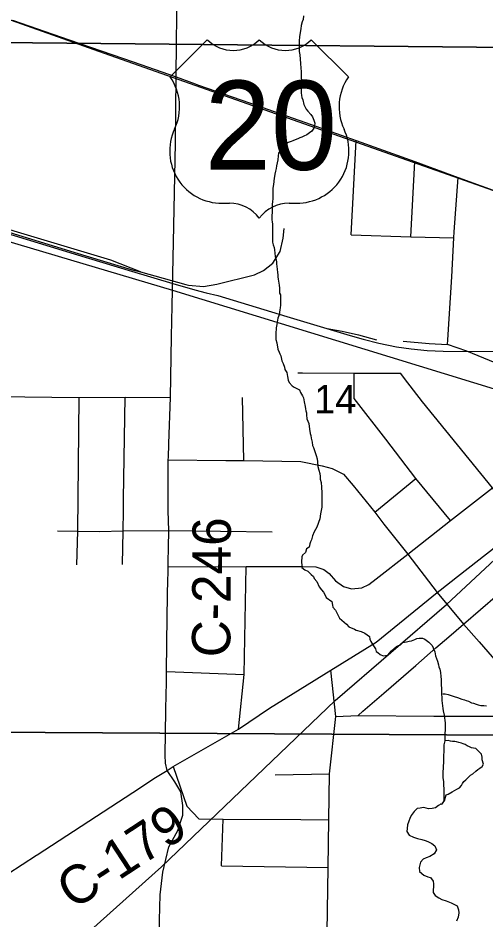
# Model space of a CAD drawing. Extents: x 0 to 34, y 0 to 22.
# Drawn here: x 6.537 to 7.229, y 17.171 to 18.505 of the extents above; entities that cross this region are included whole.
import ezdxf

# ---------------------------------------------------------------- set-up
doc = ezdxf.new("R2010")
doc.units = 0
for name, color, linetype in [('GM_X_City_Street', 7, 'Continuous'), ('GM_X_County_Road', 7, 'Continuous'), ('GM_X_County_Road_Text', 7, 'Continuous'), ('GM_X_Minor_River', 7, 'Continuous'), ('GM_X_Rail_Line', 7, 'Continuous'), ('GM_X_Section', 7, 'Continuous'), ('GM_X_Section_Text', 7, 'Continuous'), ('GM_X_Township_Road', 7, 'Continuous'), ('GM_X_US_Location', 7, 'Continuous'), ('GM_X_US_Route', 7, 'Continuous'), ('GM_X_US_Shield', 7, 'Continuous')]:
    doc.layers.add(name, color=color, linetype=linetype)

msp = doc.modelspace()

# ---------------------------------------------------------------- linework, layer by layer
at = {"layer": 'GM_X_City_Street'}
for p, q in [((7.0299, 18.1841), (7.0374, 18.3239)), ((7.1181, 18.1814), (7.1241, 18.2926)), ((6.8714, 17.8506), (6.8692, 17.9435)), ((7.0648, 17.774), (7.1257, 17.8238)), ((6.7603, 17.7469), (6.9132, 17.7448)), ((6.7567, 17.5386), (6.8716, 17.534)), ((6.9176, 17.3858), (6.9978, 17.387)), ((6.838, 17.2511), (6.8405, 17.3201)), ((6.838, 17.2511), (6.9958, 17.2486))]:
    msp.add_line(p, q, dxfattribs=at)
for points in [[(7.0299, 18.1841), (7.1181, 18.1814), (7.1818, 18.1799)], [(7.1068, 18.0268), (7.1456, 18.0236), (7.1726, 18.0219)], [(7.2836, 17.7541), (7.2391, 17.8103), (7.1354, 17.9374), (7.109, 17.9718), (7.1035, 17.9791), (7.0343, 17.9794), (6.9579, 17.9797), (6.9509, 17.9797)], [(7.1768, 17.7617), (7.1257, 17.8238), (7.0811, 17.8823), (7.0342, 17.9423), (7.0343, 17.9794)], [(6.7594, 17.8514), (6.8445, 17.8503), (6.8714, 17.8506), (6.9553, 17.8489), (6.9869, 17.8427), (7.0017, 17.8385), (7.0187, 17.8302), (7.0332, 17.8134), (7.0648, 17.774), (7.0782, 17.7562), (7.1139, 17.7119), (7.1572, 17.6552), (7.1963, 17.6084), (7.2194, 17.5823), (7.2451, 17.5529), (7.2515, 17.5456), (7.2556, 17.5403), (7.2576, 17.5341), (7.2582, 17.523), (7.2569, 17.4725), (7.2511, 17.4066)], [(7.0405, 17.4732), (7.0472, 17.4797), (7.0785, 17.5066), (7.1258, 17.5472), (7.1555, 17.5732), (7.1743, 17.5898), (7.1963, 17.6084), (7.2467, 17.6518), (7.3835, 17.7695), (7.3914, 17.7751), (7.4006, 17.7802), (7.4207, 17.7892), (7.4647, 17.8093), (7.5075, 17.8298), (7.513, 17.8322)], [(6.7593, 17.6931), (6.8745, 17.6936), (6.9179, 17.6936), (6.9583, 17.6938), (6.9776, 17.6931), (6.9897, 17.6892), (6.9975, 17.6834), (7.0069, 17.6724), (7.0186, 17.664), (7.0303, 17.6607), (7.0459, 17.6621), (7.0561, 17.6672), (7.0669, 17.6754), (7.1139, 17.7119), (7.1768, 17.7617), (7.2391, 17.8103)], [(6.8632, 17.4533), (6.8716, 17.534), (6.8745, 17.6936)], [(7.0072, 17.472), (7.0405, 17.4732), (7.1522, 17.4725), (7.2569, 17.4725), (7.3227, 17.4727)], [(6.7665, 17.3977), (6.7867, 17.3393), (6.8048, 17.3204), (6.8405, 17.3201), (6.9556, 17.3194), (6.9968, 17.319)]]:
    msp.add_lwpolyline(points, dxfattribs=at)
at = {"layer": 'GM_X_County_Road'}
for p, q in [((7.1825, 18.1889), (7.1881, 18.2693)), ((6.7624, 17.9435), (6.7641, 18.0341)), ((6.4655, 17.9453), (6.6276, 17.9439)), ((6.7595, 17.8553), (6.7602, 17.8746)), ((6.7405, 17.3814), (6.7575, 17.3922)), ((6.7067, 17.3597), (6.7405, 17.3814)), ((6.5219, 17.2393), (6.5642, 17.2669))]:
    msp.add_line(p, q, dxfattribs=at)
for points in [[(6.7641, 18.0341), (6.7649, 18.0794), (6.7671, 18.1737), (6.7702, 18.3199), (6.7709, 18.4179)], [(7.173, 18.0289), (7.179, 18.1222), (7.1818, 18.1799), (7.1825, 18.1889)], [(7.3075, 17.9794), (7.2872, 17.9796), (7.2731, 17.9796), (7.2661, 17.9826), (7.2431, 17.995), (7.2012, 18.012), (7.1726, 18.0219), (7.173, 18.0289)], [(6.6276, 17.9439), (6.6953, 17.9441), (6.7624, 17.9435)], [(6.7602, 17.8746), (6.7602, 17.8756), (6.7624, 17.9435)], [(7.1618, 17.6588), (7.1875, 17.6787), (7.246, 17.7246), (7.2836, 17.7541), (7.3286, 17.7895), (7.3789, 17.8287), (7.3933, 17.8405), (7.4314, 17.8737), (7.452, 17.8902), (7.4686, 17.899), (7.4829, 17.9074), (7.5178, 17.9352)], [(6.7593, 17.8347), (6.7593, 17.8367), (6.7594, 17.8514), (6.7595, 17.8553)], [(6.7594, 17.776), (6.7593, 17.778), (6.759, 17.7887), (6.7593, 17.8347)], [(6.7593, 17.697), (6.7594, 17.7), (6.7596, 17.7216), (6.7603, 17.7469), (6.7594, 17.776)], [(6.7589, 17.6775), (6.759, 17.6804), (6.7593, 17.6931), (6.7593, 17.697)], [(6.7565, 17.5201), (6.7566, 17.525), (6.7567, 17.5386), (6.7576, 17.62), (6.7589, 17.6775)], [(6.7575, 17.3922), (6.7665, 17.3977), (6.8632, 17.4533), (6.9092, 17.4844), (7, 17.5404), (7.0669, 17.5816), (7.1572, 17.6552), (7.1618, 17.6588)], [(6.9943, 16.6777), (6.9929, 17.0382), (6.994, 17.1215), (6.9958, 17.2486), (6.9968, 17.319), (6.9978, 17.387), (7.0072, 17.472), (7, 17.5404)], [(6.7559, 17.4808), (6.7564, 17.5055), (6.7565, 17.5201)], [(6.7575, 17.3922), (6.7551, 17.4027), (6.7546, 17.4145), (6.7559, 17.4808)], [(6.7374, 17.0638), (6.7393, 17.0697), (6.7425, 17.084), (6.7456, 17.1033), (6.7462, 17.1319), (6.7464, 17.1706), (6.7473, 17.2079), (6.7515, 17.2415), (6.7604, 17.279), (6.7736, 17.3034), (6.7807, 17.3258), (6.7807, 17.3402), (6.7779, 17.3604), (6.7688, 17.3754), (6.7575, 17.3922)], [(6.5642, 17.2669), (6.5651, 17.2675), (6.7067, 17.3597)]]:
    msp.add_lwpolyline(points, dxfattribs=at)
at = {"layer": 'GM_X_Minor_River'}
for points in [[(6.9593, 18.5082), (6.9589, 18.5028), (6.9574, 18.4994), (6.9559, 18.4941), (6.9556, 18.4892), (6.9544, 18.4838), (6.9533, 18.477), (6.953, 18.4713), (6.9531, 18.4553), (6.9542, 18.4504), (6.9551, 18.4379), (6.9555, 18.4307), (6.9559, 18.4261), (6.9559, 18.4193), (6.9563, 18.4102), (6.9564, 18.4041), (6.956, 18.3984), (6.956, 18.3942), (6.9564, 18.3904), (6.9568, 18.3874), (6.9584, 18.384), (6.9599, 18.3771), (6.9634, 18.3703), (6.966, 18.3673), (6.9702, 18.3624), (6.9729, 18.3586), (6.9748, 18.3537), (6.976, 18.3495), (6.9756, 18.3453), (6.9749, 18.3419), (6.9719, 18.3377), (6.9685, 18.335), (6.9643, 18.3323), (6.9601, 18.3304), (6.9571, 18.3289), (6.9541, 18.3277), (6.9511, 18.3262), (6.9473, 18.3247), (6.9439, 18.3231), (6.9412, 18.3224), (6.937, 18.3208), (6.9344, 18.3193), (6.9317, 18.3162), (6.9291, 18.3136), (6.9265, 18.3113), (6.9242, 18.3082), (6.9227, 18.3052), (6.9219, 18.301), (6.9216, 18.2953), (6.9194, 18.2862), (6.919, 18.2824), (6.9179, 18.2786), (6.9168, 18.274), (6.9164, 18.2706), (6.916, 18.2679), (6.9153, 18.2588), (6.9142, 18.2535), (6.9142, 18.2455), (6.9139, 18.2406), (6.9139, 18.2379), (6.9136, 18.233), (6.9132, 18.2295), (6.9132, 18.2257), (6.9129, 18.2212), (6.9129, 18.2166), (6.9125, 18.2132), (6.9125, 18.2064), (6.9129, 18.2033), (6.9137, 18.1999), (6.9138, 18.1882), (6.9138, 18.1844), (6.9138, 18.1737), (6.9146, 18.1695), (6.9158, 18.1654), (6.9166, 18.1623), (6.917, 18.157), (6.9177, 18.1525), (6.9189, 18.1472), (6.9193, 18.1441), (6.9197, 18.1415), (6.9201, 18.1377), (6.9205, 18.1335), (6.9209, 18.1286), (6.9217, 18.1251), (6.9217, 18.1221), (6.9221, 18.1187), (6.9229, 18.113), (6.9233, 18.11), (6.9237, 18.1054), (6.9237, 18.1008), (6.9241, 18.0982), (6.9252, 18.0955), (6.9253, 18.0803), (6.925, 18.0762), (6.9246, 18.0735), (6.9235, 18.0659), (6.9216, 18.0609), (6.9205, 18.0552), (6.9201, 18.0518), (6.919, 18.0469), (6.9187, 18.0381)], [(6.9187, 18.0381), (6.9183, 18.0324), (6.9187, 18.0294), (6.9199, 18.0245), (6.9215, 18.0154), (6.9234, 18.0108), (6.9242, 18.0082), (6.9257, 18.0055), (6.9272, 17.9979), (6.9292, 17.9938), (6.9315, 17.9888), (6.9319, 17.985), (6.9349, 17.9805), (6.9357, 17.9748), (6.9369, 17.9695), (6.938, 17.9657), (6.9426, 17.9608), (6.9457, 17.9589), (6.9506, 17.9563), (6.9533, 17.9551), (6.9552, 17.9513), (6.9582, 17.946), (6.9594, 17.943), (6.9606, 17.9373), (6.9617, 17.9305), (6.9625, 17.9267), (6.9629, 17.924), (6.9637, 17.921), (6.9641, 17.9183), (6.9645, 17.9123), (6.9672, 17.9051), (6.9684, 17.8971), (6.9691, 17.8903), (6.9703, 17.8876), (6.9707, 17.8838), (6.9723, 17.8774), (6.973, 17.8728), (6.9742, 17.8698), (6.9761, 17.8637), (6.978, 17.858), (6.9796, 17.8531), (6.9804, 17.8485), (6.9808, 17.8417), (6.9819, 17.8364), (6.9835, 17.8311), (6.9839, 17.8269), (6.9843, 17.8231), (6.9855, 17.8178), (6.9859, 17.8113), (6.9863, 17.8087), (6.9867, 17.8053), (6.9868, 17.7859), (6.9864, 17.7813), (6.9845, 17.7714), (6.9838, 17.7642), (6.9793, 17.752), (6.9752, 17.7448), (6.9729, 17.7391), (6.9714, 17.7334), (6.9699, 17.7304), (6.9688, 17.7273), (6.9677, 17.7224), (6.9639, 17.7197), (6.9624, 17.7144), (6.9579, 17.7105), (6.9568, 17.7079), (6.9564, 17.7007), (6.9572, 17.695), (6.9572, 17.6923), (6.9614, 17.6889), (6.966, 17.687), (6.9706, 17.6817), (6.9744, 17.6791), (6.9751, 17.6761), (6.9793, 17.6715), (6.9824, 17.6639), (6.9862, 17.659), (6.9889, 17.656), (6.9912, 17.6522), (6.9931, 17.648), (7.0015, 17.642), (7.0023, 17.6367), (7.0027, 17.6337), (7.0069, 17.6291), (7.0126, 17.6174), (7.0229, 17.6083), (7.0264, 17.6045), (7.0347, 17.6008), (7.0374, 17.5996), (7.045, 17.5974), (7.05, 17.5951), (7.0572, 17.5902), (7.0576, 17.5864), (7.0591, 17.583), (7.0622, 17.5781), (7.066, 17.572), (7.0668, 17.5679), (7.0695, 17.5664), (7.0729, 17.5637), (7.0774, 17.5618), (7.0809, 17.5619)], [(7.0809, 17.5619), (7.0843, 17.5626), (7.0896, 17.5691), (7.0971, 17.5756), (7.0998, 17.5771), (7.1032, 17.5779), (7.1066, 17.5813), (7.1119, 17.5825), (7.1157, 17.5833), (7.1191, 17.5837), (7.1244, 17.5856), (7.1274, 17.5871), (7.1308, 17.5879), (7.1358, 17.5879), (7.1388, 17.5864), (7.1449, 17.5819), (7.1499, 17.577), (7.1537, 17.5675), (7.1549, 17.5614), (7.158, 17.5539), (7.1591, 17.5482), (7.1599, 17.5451), (7.1614, 17.5417), (7.1622, 17.5368), (7.1626, 17.5311), (7.163, 17.5265), (7.1631, 17.5227), (7.1635, 17.5094), (7.1643, 17.4954), (7.1655, 17.4836), (7.1659, 17.4802), (7.1675, 17.4738), (7.1687, 17.4662), (7.169, 17.4624), (7.1691, 17.4563), (7.1688, 17.4426), (7.1684, 17.4358), (7.1673, 17.4301), (7.1673, 17.4274), (7.167, 17.4213), (7.1666, 17.4134), (7.1667, 17.4092), (7.1667, 17.4046), (7.166, 17.3974), (7.166, 17.3944), (7.1656, 17.3909), (7.1657, 17.3814), (7.1664, 17.3754), (7.1665, 17.3716), (7.1673, 17.3632), (7.1673, 17.3606), (7.1669, 17.3564), (7.167, 17.3492), (7.1666, 17.3461), (7.164, 17.3419), (7.1624, 17.3424)], [(7.1658, 17.5054), (7.1692, 17.5054), (7.1734, 17.5042), (7.1764, 17.5034), (7.1794, 17.5023), (7.1824, 17.5015), (7.1873, 17.4999), (7.1938, 17.4976), (7.1976, 17.4964), (7.2002, 17.4953), (7.2036, 17.4945), (7.2081, 17.4922), (7.2112, 17.4914), (7.215, 17.4902), (7.218, 17.489), (7.2221, 17.4882), (7.2263, 17.4882), (7.2301, 17.4878)], [(7.1648, 17.3429), (7.1686, 17.3479), (7.1698, 17.3528), (7.1706, 17.3562), (7.1733, 17.3569), (7.1797, 17.3603), (7.1828, 17.3625), (7.1862, 17.3644), (7.1904, 17.3666), (7.1931, 17.37), (7.195, 17.3727), (7.1969, 17.3757), (7.1996, 17.3783), (7.2027, 17.381), (7.2065, 17.3851), (7.2099, 17.387), (7.2145, 17.3911), (7.2172, 17.3937), (7.2206, 17.3956), (7.2237, 17.3979), (7.2256, 17.4016), (7.2241, 17.4077), (7.2238, 17.4119), (7.2227, 17.4161), (7.2144, 17.4245), (7.211, 17.4249), (7.208, 17.4257), (7.2049, 17.4269), (7.2019, 17.4284), (7.1985, 17.4304), (7.1959, 17.4315), (7.1932, 17.4323), (7.1894, 17.4335), (7.186, 17.4346), (7.1834, 17.4347), (7.18, 17.4351), (7.1769, 17.4355), (7.1735, 17.4366), (7.1686, 17.4359)], [(7.1625, 17.3422), (7.159, 17.34), (7.1549, 17.3366), (7.1499, 17.3358), (7.1446, 17.3354), (7.1408, 17.3365), (7.137, 17.3372), (7.1321, 17.3365), (7.1275, 17.3357), (7.1234, 17.3315), (7.1189, 17.3254), (7.1166, 17.3208), (7.1151, 17.317), (7.1136, 17.3117), (7.1129, 17.3064), (7.1125, 17.3018), (7.116, 17.2965), (7.1221, 17.2935), (7.1281, 17.2916), (7.1346, 17.2898), (7.1396, 17.2886), (7.1434, 17.2868), (7.1494, 17.2841), (7.1536, 17.2807), (7.1563, 17.2747), (7.1529, 17.2686), (7.1465, 17.2647), (7.1412, 17.2628), (7.1363, 17.2609), (7.1325, 17.2563), (7.1314, 17.2525), (7.1306, 17.2483), (7.1311, 17.2426), (7.1375, 17.2373), (7.1436, 17.2347), (7.1474, 17.2336), (7.1512, 17.2283), (7.152, 17.2245), (7.1517, 17.2196), (7.1513, 17.2158), (7.1513, 17.2116), (7.1544, 17.207), (7.1597, 17.2036), (7.1643, 17.2014), (7.1704, 17.1991), (7.178, 17.1965), (7.1829, 17.1939), (7.1867, 17.1916), (7.189, 17.1859), (7.1894, 17.1814), (7.1883, 17.1753), (7.1857, 17.1692)]]:
    msp.add_lwpolyline(points, dxfattribs=at)
at = {"layer": 'GM_X_Rail_Line'}
for points in [[(2.1, 20.1355), (2.5574, 19.9667), (3.1422, 19.7506), (3.6996, 19.5506), (4.3507, 19.3207), (4.9212, 19.1118), (5.8157, 18.7674), (6.212, 18.6139), (6.6644, 18.4531), (7.3247, 18.2205), (7.6757, 18.0934)], [(2.1, 19.5186), (2.8346, 19.2964), (3.6748, 19.0394), (4.5141, 18.7823), (5.7652, 18.3991), (6.2109, 18.2673), (6.7654, 18.1025), (7.4524, 17.8921)], [(6.4243, 18.2159), (6.6203, 18.1561), (6.7051, 18.1305), (6.7659, 18.1123), (6.7984, 18.103), (6.8153, 18.0987), (6.8327, 18.0945), (6.9348, 18.0637), (7.0286, 18.0353), (7.0478, 18.0299), (7.0709, 18.0239), (7.0972, 18.0185), (7.119, 18.0155), (7.1427, 18.0133), (7.1662, 18.0122), (7.2447, 18.0118)], [(6.718, 18.1294), (6.6742, 18.1467), (6.5315, 18.1897), (6.4552, 18.2136), (6.425, 18.2181)], [(6.425, 18.2181), (6.621, 18.1583), (6.7057, 18.1327), (6.718, 18.1294)], [(6.718, 18.1294), (6.7854, 18.1108), (6.7894, 18.1097), (6.8113, 18.1081), (6.8311, 18.1114), (6.8869, 18.1252), (6.9005, 18.1316), (6.9142, 18.1426), (6.9251, 18.1595), (6.9296, 18.1795), (6.9309, 18.1937)], [(6.9945, 18.0456), (7.0167, 18.0416), (7.0407, 18.0365), (7.0674, 18.0292)], [(3.6815, 14.4919), (3.8612, 14.6519), (4.1651, 14.9197), (4.4686, 15.1913), (4.7768, 15.471), (5.1412, 15.8006), (5.4601, 16.0872), (6.2018, 16.7592), (6.7493, 17.2493), (7.0065, 17.4955), (7.1712, 17.6375), (7.3789, 17.8309), (7.4524, 17.8921)]]:
    msp.add_lwpolyline(points, dxfattribs=at)
at = {"layer": 'GM_X_Section'}
for points in [[(6.5246, 19.4487), (7.5241, 19.4466), (7.5189, 18.4589), (6.5078, 18.4687)], [(7.5189, 18.4589), (7.5107, 17.4428), (6.4919, 17.4489), (6.5078, 18.4687)], [(6.4919, 17.4489), (7.5107, 17.4428), (7.4967, 16.4401), (6.481, 16.4419)]]:
    msp.add_lwpolyline(points, close=True, dxfattribs=at)
at = {"layer": 'GM_X_Township_Road'}
msp.add_line((6.5955, 17.7465), (6.6244, 17.7461), dxfattribs=at)
for points in [[(6.7709, 18.4179), (6.771, 18.421), (6.7725, 18.5555)], [(6.6238, 17.6963), (6.6253, 17.7461), (6.6276, 17.9439)], [(6.6929, 17.7761), (6.693, 17.7939), (6.6953, 17.9441)], [(6.6915, 17.6967), (6.6926, 17.7465), (6.6929, 17.7761)], [(6.6244, 17.7461), (6.6253, 17.7461), (6.6578, 17.7453), (6.6926, 17.7465), (6.7603, 17.7469)]]:
    msp.add_lwpolyline(points, dxfattribs=at)
at = {"layer": 'GM_X_US_Route'}
for points in [[(6.5287, 18.5018), (6.6127, 18.4729), (6.7072, 18.4402), (6.7709, 18.4179), (6.7993, 18.4076)], [(6.7993, 18.4076), (6.8041, 18.4059), (6.8793, 18.3795), (6.9706, 18.3476), (7.0374, 18.3239), (7.1241, 18.2926), (7.1881, 18.2693), (7.2563, 18.2446), (7.3266, 18.219), (7.3939, 18.1948), (7.4219, 18.1846), (7.5199, 18.149)]]:
    msp.add_lwpolyline(points, dxfattribs=at)
at = {"layer": 'GM_X_US_Shield'}
for p, q in [((6.8171, 18.4728), (6.7622, 18.4178)), ((7.0259, 18.4178), (6.971, 18.4728)), ((6.8391, 18.2311), (6.8501, 18.2311)), ((6.938, 18.2311), (6.949, 18.2311))]:
    msp.add_line(p, q, dxfattribs=at)
for centre, radius, start, end in [((6.8556, 18.512), 0.0549, 225.573, 314.427), ((6.9325, 18.512), 0.0549, 225.573, 314.427), ((6.6992, 18.3737), 0.0769, 334.5471, 35.0009), ((7.0889, 18.3737), 0.0769, 144.9991, 205.4529), ((6.8383, 18.308), 0.0769, 154.8319, 270.6383), ((6.9498, 18.308), 0.0769, 269.3617, 25.1681), ((6.8501, 18.1761), 0.0549, 36.8699, 90), ((6.938, 18.1761), 0.0549, 90, 143.1301)]:
    msp.add_arc(centre, radius, start, end, dxfattribs=at)

# ---------------------------------------------------------------- texts
at = {"layer": 'GM_X_County_Road_Text'}
for s, rotation, p in [('C-246', 89.7233, (6.8511, 17.5594)), ('C-179', 33.1867, (6.6189, 17.185))]:
    msp.add_text(s, height=0.05682, rotation=rotation, dxfattribs=at).set_placement(p)
at = {"layer": 'GM_X_Section_Text'}
msp.add_text('14', height=0.04186, rotation=0, dxfattribs=at).set_placement((6.9753, 17.9204))
at = {"layer": 'GM_X_US_Location'}
for s in ['0', '/']:
    msp.add_text(s, height=0.000189, dxfattribs=at).set_placement((6.894, 18.3454))
msp.add_text('20', height=0.000189, rotation=0, dxfattribs=at).set_placement((6.8549, 18.3062))
at = {"layer": 'GM_X_US_Shield'}
msp.add_text('20', height=0.13184, dxfattribs=at).set_placement((6.8131, 18.2805))

doc.saveas('drawing.dxf')
